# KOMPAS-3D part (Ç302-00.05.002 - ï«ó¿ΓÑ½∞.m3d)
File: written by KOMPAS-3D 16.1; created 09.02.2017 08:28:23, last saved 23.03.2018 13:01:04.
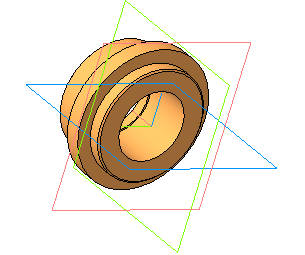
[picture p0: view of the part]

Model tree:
1. Эскиз:24
2. Операция вращения:2
     Угол 1 = 360
3. Фаска:1  (labels: Фторопласт-4  ГОСТ 10007-80 Е)
     Угол = 45; Длина 1 = 0.5; Длина 2 = 0.5

Expressions: 9+1
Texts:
  Body Specification ( left align )
  Body Specificaton ( centered )
  Линейный размер с обрывом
